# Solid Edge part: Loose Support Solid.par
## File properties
Author: davee
Template: Normal.par
Last saved by: davee
Revision: 5
Application: Solid Edge
Accuracy: 0.990
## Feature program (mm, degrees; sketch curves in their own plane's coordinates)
body "unnamed Body 1"
sketch for "unnamed Cutout 1" plane through (0, -40, -2.125) normal (0, -1, 0) x-axis (1, 0, 0)
  line (-6.001, 8.125) -> (6.001, 8.125)
extrude "unnamed Cutout 1" cut finite 158.75 along -normal
delete faces "unnamed DeleteFaces 1"
fillet "Round_2" radius 1
delete faces "unnamed DeleteFaces 2"
sketch for "unnamed Protrusion 1" plane through (0, 5.25, -10) normal (0, 0, -1) x-axis (0, 1, 0)
extrude "unnamed Protrusion 1" add to key point along -normal
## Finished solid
Body 1: solid body, 26 faces, 56 edges, 32 vertices.
  Faces by surface: cylinder 12, torus 8, plane 6
  Edges by curve: circle 32, line 24
Bounding box of the edges (mm; curved faces can reach further): 38.000 x 90.500 x 16.000, from (-19, -40, -10) to (19, 50.5, 6).
Cylindrical faces by radius (mm): R0.75 x4, R1 x4, R1.5 x2, R3 x2
Toroidal faces (ring radius, tube radius in mm): R0.5 r1 x2, R0.75 r0.75 x2, R2 r1 x2, R2.25 r0.75 x2
Planar faces by outward normal: +x 1, +y 1, +z 1, -x 1, -y 1, -z 1
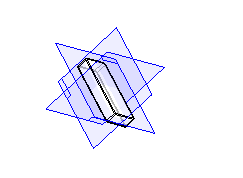
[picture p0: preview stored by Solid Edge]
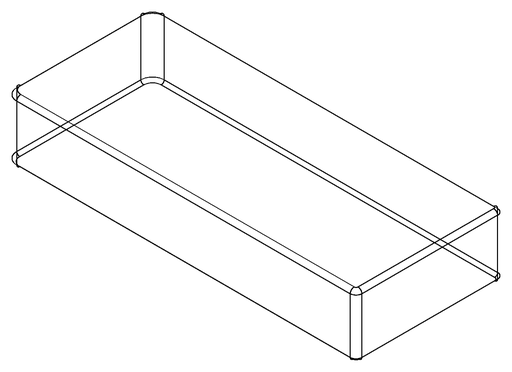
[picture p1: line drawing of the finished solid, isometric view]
